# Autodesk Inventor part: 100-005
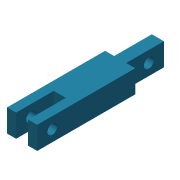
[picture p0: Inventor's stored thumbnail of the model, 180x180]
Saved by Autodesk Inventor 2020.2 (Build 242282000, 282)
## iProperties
Created: 2014-01
Part Number: 100-005
Material: Ogólny
Document SubType Name: Modeling
Designer: F.Stasiak
Density: 1 g/cm^3
Appearance: Turkusowa
Manager: www.cadconsulting.pl
Company: Fabian Stasiak CAD Consulting
Author: F.Stasiak
Subject: Zbiór ćwiczeń. Autodesk Inventor 2020. Kurs podstawowy
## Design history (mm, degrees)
sketch "Szkic1"
  geometry: L1 (-10, 7.5)-(10, 7.5); L2 (10, 7.5)-(10, -7.5); L3 (10, -7.5)-(-10, -7.5); L4 (-10, -7.5)-(-10, 7.5); L5 (-10, 7.5)-(10, -7.5); L6 (10, 7.5)-(-10, -7.5); 1 further point
  constraints: 12 end point, 2 midpoint, 2 parallel, 1 horizontal, 1 perpendicular
  dimensions: "d0" = 20 distance of L2.end L3.end; "d1" = 15 distance of L1.end L2.end
extrude "Wyciągnięcie proste1" new body sketch "Szkic1" distance "d2" = 40; taper "d3" = 0 deg
sketch "Szkic2"
  geometry: L1 (10, 7.5)-(-10, 7.5) reference; L2 (-10, 7.5)-(-10, -7.5) reference; L3 (-10, -7.5)-(10, -7.5) reference; L4 (10, -7.5)-(10, 7.5) reference; L5 (-4, 7.5)-(-4, -7.5); L6 (4, -7.5)-(4, 7.5); L7 (-4, 0)-(4, 0); 2 further points
  constraints: 6 end point, 4 point on line, 3 midpoint, 2 perpendicular, 1 coincident
  dimensions: "d4" = 8 distance between parallel lines of L6 L5
extrude "Wyciągnięcie proste2" join sketch "Szkic2" distance "d5" = 25; taper "d6" = 0 deg
sketch "Szkic3"
  geometry: L1 (-65, 0)-(-65, 15) reference; 3 further points
  constraints: 1 horizontal alignment, 1 midpoint
  dimensions: "d7" = 10 distance from line of point (-55, 7.5) L1
hole "Otwór1" sketch "Szkic3" at (-55, 7.5) diameter "d8" = 6.5; stored, may be unused: countersink angle "d12" = 90 deg, drill point angle "d14" = 118 deg; dims "d9" = 6, "d10" = 4, "d11" = 2, "d13" = 8
sketch "Szkic4"
  geometry: L1 (10, 7.5)-(-10, 7.5) reference; L2 (-10, -7.5)-(10, -7.5) reference; L3 (4, -7.5)-(4, 7.5) reference; L4 (-4, 7.5)-(-4, -7.5) reference; 1 further point
extrude "Wyciągnięcie proste3" join sketch "Szkic4" distance "d15" = 25; taper "d16" = 0 deg
sketch "Szkic5"
  geometry: L1 (-95, 15)-(-95, 0) reference; 2 further points
  constraints: 1 horizontal alignment, 1 midpoint
  dimensions: "d25" = 10 distance from line of L1 point (-105, 7.5)
hole "Otwór2" sketch "Szkic5" at (-105, 7.5) diameter "d24" = 6.5; stored, may be unused: drill point angle "d19" = 118 deg, countersink angle "d20" = 90 deg; dims "d17" = 6, "d21" = 2, "d22" = 4, "d23" = 8
node "Bryła1"
